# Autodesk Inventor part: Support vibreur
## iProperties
Created: 2010-07
Part Number: Support vibreur
Document SubType Name: Modeling
Designer: eric
Density: 1 g/cm^3
Mass: 4.86421 g
Surface Area: 41.7074 cm^2
Volume: 4.86421 cm^3
Author: eric
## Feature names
1. Extrusion6
2. Extrusion5
3. Extrusion4
4. Extrusion3
5. Extrusion2
6. Extrusion1
7. Revolution3
8. Revolution2
9. Revolution1
10. Hole1
11. Fillet4
12. Fillet3
13. Fillet2
14. Fillet1
